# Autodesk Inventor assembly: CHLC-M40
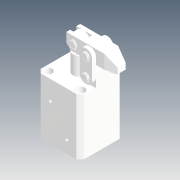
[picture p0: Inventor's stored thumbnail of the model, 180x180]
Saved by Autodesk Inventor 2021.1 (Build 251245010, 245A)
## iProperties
Company: Microsoft
Created: 2019-11
Part Number: CHLC-M40
Description: STEP AP214
Document SubType Name: Assembly
Designer: user
Title: CHLC-M40.STEP
Author: Windows
Revision Number: ÈÎºÎ
Sending System: SolidWorks 2015
Preprocessor: SwSTEP 2.0
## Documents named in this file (9)
- D:\Vault_2016\Projekty\Clamptek\Hydraulic\CHLC\CHLC-40\Inventor\CHLC-M40\CHLC-M40.iam
- D:\Vault_2016\Projekty\Clamptek\Hydraulic\CHLC\CHLC-40\Inventor\CHLC-M40\CHLC-M40-05.ipt
- D:\Vault_2016\Projekty\Clamptek\Hydraulic\CHLC\CHLC-40\Inventor\CHLC-M40\CHLC-40-08.ipt
- D:\Vault_2016\Projekty\Clamptek\Hydraulic\CHLC\CHLC-40\Inventor\CHLC-M40\CHLC-40-01.ipt
- D:\Vault_2016\Projekty\Clamptek\Hydraulic\CHLC\CHLC-40\Inventor\CHLC-M40\CHLC-40-03.ipt
- D:\Vault_2016\Projekty\Clamptek\Hydraulic\CHLC\CHLC-40\Inventor\CHLC-M40\CHLC-40-02.ipt
- D:\Vault_2016\Projekty\Clamptek\Hydraulic\CHLC\CHLC-40\Inventor\CHLC-M40\CHLC-40-04.ipt
- D:\Vault_2016\Projekty\Clamptek\Hydraulic\CHLC\CHLC-40\Inventor\CHLC-M40\CHLC-40-06.ipt
- D:\Vault_2016\Projekty\Clamptek\Hydraulic\CHLC\CHLC-40\Inventor\CHLC-M40\M6LS.ipt
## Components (16 placed, 16 different names)
1. CHLC-M40-05_1
2. CHLC-40-08_2
3. CHLC-40-01_3
4. CHLC-40-03_4
5. CHLC-40-03_5
6. CHLC-40-02_6
7. CHLC-40-02_7
8. CHLC-40-04_8
9. CHLC-40-06_9
10. CHLC-40-06_10
11. CHLC-40-06_11
12. CHLC-40-06_12
13. CHLC-40-06_13
14. CHLC-40-06_14
15. M6LS_15
16. M6LS_16
